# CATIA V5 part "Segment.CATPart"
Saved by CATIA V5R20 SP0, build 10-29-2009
Part number: Segment
Bounding box of the stored display mesh (mm): x 0 to 2, y 8.113 to 9.94, z 1.582 to 10.454
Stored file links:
  C:\Users\MATT\Desktop\CATIA_Projet_IAO\CATIA FINAL\Segment.CATPart
  C:\Users\MATT\Desktop\CATIA_Projet_IAO\CATIA FINAL\mderemetz.CATProduct
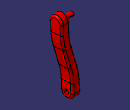
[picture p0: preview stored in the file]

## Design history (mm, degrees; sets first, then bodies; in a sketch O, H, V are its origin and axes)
External parameters (linked from other documents)
  External.AC = 3 mm
  `External.Paramètre2` = 2.46 mm
  External.CoeffAC = 3
  External.Epaisseur = 1 mm
Set1
  Plane1 "Plan_Sec": linked copy from another document
  Point1 "E": linked copy from another document
  Line1 "Segment_ED": linked copy from another document
  Plane2 "Plan_Ter": linked copy from another document
  Point2 "D": linked copy from another document
  Plane3 "Plan_Ref": linked copy from another document
  Line2 "Axe_E_segment": linked copy from another document
Body1 (main body)
  Sketch1 on Plane1, origin (1, 0, 0), H (0, 1, 0), V (0, 0, 1)
    construction line L1 (8.8626, 9.7044) -> (9.6182, -7.2793)
    point P1 (8.8626, 9.7044)
    line L2 (9.6118, 9.7378) -> (9.8579, 4.2082)
    line L3 (8.3594, 4.1416) -> (8.1133, 9.6711)
    arc A1 centre (8.8626, 9.7044) radius 0.75 from (8.1133, 9.6711) to (9.6118, 9.7378) cw
    line L4 (9.8579, 4.2082) -> (8.3594, 4.1416)
    reference projected point E1 (8.8626, 9.7044) from Point1
    reference projected line E2 (9.7372, -9.9531) -> (9.4092, -2.5804) from Line1
    distance L3 L2 = 1.5 {= 1.5*External.AC /3}
    length L2 = 5.535 {= 0.75*`External.Paramètre2` *External.CoeffAC}
    tangency: A1 L2, A1 L3
    parallelism: L1 L2
    perpendicularity: L3 L4, L4 L2
    coincidence: P1 E1, L1 E2
  Pad1: profile Sketch1, direction (1, 0, 0), up to Plane2
  Sketch2 on Plane1, origin (1, 0, 0), H (0, 1, 0), V (0, 0, 1)
    construction line L1 (9.6465, -7.9142) -> (9.1906, 2.3317)
    point P2 (9.1906, 2.3317)
    line L2 (9.6938, 7.8946) -> (9.9399, 2.365)
    line L3 (8.4414, 2.2984) -> (8.1953, 7.8279)
    arc A1 centre (9.1906, 2.3317) radius 0.75 from (9.9399, 2.365) to (8.4414, 2.2984) cw
    line L4 (8.1953, 7.8279) -> (9.6938, 7.8946)
    reference projected point E1 (9.1906, 2.3317) from Point2
    reference projected line E2 (9.7372, -9.9531) -> (9.4092, -2.5804) from Line1
    distance L3 L2 = 1.5 {= 1.5*External.AC /3}
    length L2 = 5.535 {= 0.75*`External.Paramètre2` *External.CoeffAC}
    tangency: A1 L2, A1 L3
    parallelism: L1 L2, E2 L2
    perpendicularity: L4 L1
    coincidence: P2 E1
  Pad2: profile Sketch2, direction (1, 0, 0), up to Plane3
  Sketch3 on face of Pad1, origin (0, 10.1849, -3.1427), H (-1, 0, 0), V (0, -0.0444, 0.999)
    point P1 (-1, 11.0482)
    line L1 (-1, 11.0482) -> (0, 7.3582)
    point P2 (0, 7.3582)
    line L2 (-1, 11.0482) -> (2, 11.0482)
    line L3 (0, 7.3582) -> (2, 7.3582)
    line L4 (2, 7.3582) -> (2, 11.0482)
    point P5 (-2, 12.8932)
    reference intersected line E1 through (-2, 0) direction (0, -1) from Plane2
    reference projected line E2 (5, 12.8932) -> (-5, 12.8932) from Line2
    reference projected line E3 (5, 12.8932) -> (-5, 12.8932) from Line2
    reference intersected line E4 through (-1, 0) direction (0, -1) from Plane1
    reference projected point E5 (0, 5.5132) from Point2
    reference intersected line E6 through (0, 0) direction (0, -1) from Plane3
    line L5 (-4, 11.0482) -> (-2, 11.0482)
    point P7 (-2, 11.0482)
    line L6 (-4, 11.0482) -> (-4, 7.3582)
    line L7 (-4, 7.3582) -> (-1, 7.3582)
    point P9 (-1, 7.3582)
    line L8 (-1, 7.3582) -> (-2, 11.0482)
    reference projected point E7 (0, 12.8932) from Point1
    reference projected point E8 (0, 5.5132) from Point2
    reference intersected line E9 through (-2, 0) direction (0, -1) from Plane2
    reference intersected line E10 through (-1, 0) direction (0, -1) from Plane1
    distance L2 E3 = 1.845 {= 0.25*`External.Paramètre2` *External.CoeffAC}
    distance L3 E5 = 1.845 {= 0.25*`External.Paramètre2` *External.CoeffAC}
    length L3 = 2
    distance L5 E7 = 1.845 {= 0.25*`External.Paramètre2` *External.CoeffAC}
    distance L7 E8 = 1.845 {= 0.25*`External.Paramètre2` *External.CoeffAC}
    length L5 = 2
    horizontal: L2 H, L3 H, L5 H, L7 H
    vertical: L4 V, L6 V
    coincidence: P5 E1, P5 E2, P1 E4, P2 E6, P7 E9, P9 E10
  Pocket1: profile Sketch3, direction (0, -0.999, -0.0444), through (limit type 3)
  Fillet1: radius 6 {= 6*External.AC /3}, on edge [end face of Pad1 | face of Pocket1 from Sketch3.L8]; edge [face of Pocket1 from Sketch3.L8 | start face of Pad2]; edge [end face of Pad2 | face of Pocket1 from Sketch3.L1]; edge [face of Pocket1 from Sketch3.L1 | start face of Pad1]
  Fillet2: radius 0.2 {= 0.2*External.AC /3}, on edge [end face of Pad1 | face of Pad1]; edge [face of Fillet1 | face of Pad1]
  Sketch4 on start face of Pad1, origin (1, 0, 0), H (0, -1, 0), V (0, 0, 1)
    circle A1 centre (-8.8626, 9.7044) radius 0.25
    point P1 (-8.8626, 9.7044)
    reference projected point E1 (-8.8626, 9.7044) from Point1
    radius A1 = 0.25 {= 0.5*External.AC /6}
    coincidence: P1 E1
  Pad3: profile Sketch4, direction (-1, 0, 0), length 1 {= External.Epaisseur}
  Sketch5 on end face of Pad2, origin (0, 8.8641, 3.0226), H (0, 1, 0), V (0, 0, -1)
    point P1 (0.3265, 0.6909)
    reference projected point E1 (0.3265, 0.6909) from Point2
    coincidence: P1 E1
  Hole1: placed by Sketch5, at (0, 9.1906, 2.3317) direction (1, 0, 0), diameter 0.5 {= 0.5*External.AC /3}, through (limit type 3)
